// Mitsubishi GX Works2 project: 6DA   PLC: FX3U/FX3UC

PROGRAM MAIN
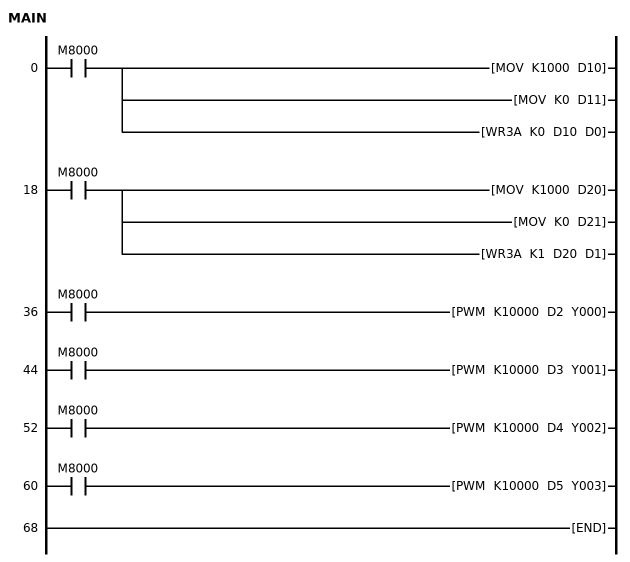
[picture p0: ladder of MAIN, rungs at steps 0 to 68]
0     LD      M8000
      MOV     K1000 D10
        [note] DA0模拟量输出D0 0-1000对应0-10V
      MOV     K0 D11
      WR3A    K0 D10 D0
18    LD      M8000
      MOV     K1000 D20
        [note] DA1模拟量输出D1 0-1000对应0-10V
      MOV     K0 D21
      WR3A    K1 D20 D1
36    LD      M8000
      PWM     K10000 D2 Y000
        [note] YDA0模拟量输出D2 0-1000对应0-10V
44    LD      M8000
      PWM     K10000 D3 Y001
        [note] YDA1模拟量输出D3 0-1000对应0-10V
52    LD      M8000
      PWM     K10000 D4 Y002
        [note] YDA2模拟量输出D4 0-1000对应0-10V
60    LD      M8000
      PWM     K10000 D5 Y003
        [note] YDA3模拟量输出D5 0-1000对应0-10V
68    END
END_PROGRAM
